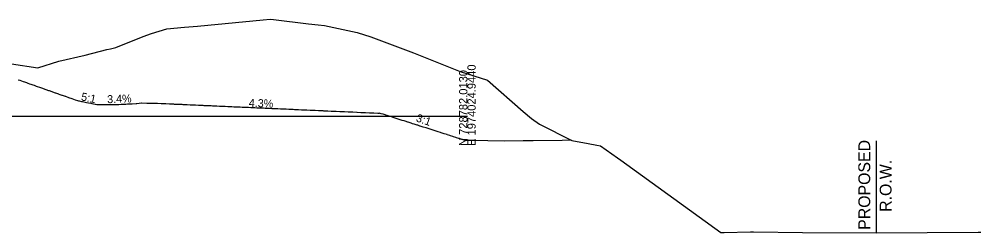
# Model space of a CAD drawing. Extents: x -26 to 630, y -39 to 9098.
# Drawn here: x 298.8 to 623.2, y 960.7 to 1032.7 of the extents above; entities that cross this region are included whole.
import ezdxf

# ---------------------------------------------------------------- set-up
doc = ezdxf.new("R2010")
doc.units = 0
for name, color, linetype in [('CONST_DCH', 7, 'Continuous'), ('Default', 7, 'Continuous'), ('DTM_X_FLOW_ARROWS', 7, 'Continuous'), ('DTM_X_GROUND', 7, 'Continuous'), ('XS_CELL', 7, 'Continuous'), ('XS_P_GROUND', 7, 'Continuous'), ('XS_P_ROW', 7, 'Continuous'), ('XS_P_TX_FS_BS', 7, 'Continuous')]:
    doc.layers.add(name, color=color, linetype=linetype)

msp = doc.modelspace()

# ---------------------------------------------------------------- linework, layer by layer
at = {"layer": 'DTM_X_GROUND'}
msp.add_lwpolyline([(296.18, 1017.68), (305.07, 1016.38), (312.1, 1018.55), (321.05, 1020.57), (328.36, 1022.58), (329.58, 1022.72), (331.34, 1023.24), (340.58, 1026.88), (343.46, 1027.9), (348.54, 1029.53), (354.5, 1030), (358.9, 1030.39), (381.1, 1032.55), (383.47, 1032.72), (384.56, 1032.65), (396.39, 1031.17), (399.69, 1030.79), (401.77, 1030.66), (412.78, 1028.2), (417.41, 1026.75), (431.84, 1021.4), (447.6, 1015.09), (456.8, 1012.18), (468.77, 1001.66), (471.65, 999.21), (474.32, 997.31), (485.24, 991.82), (490.72, 990.82), (493.73, 990.31), (494.95, 990.08), (500.68, 985.98), (501.78, 985.16), (535.48, 960.84), (536.66, 960.86), (545.52, 961.02), (546, 961.02), (546.53, 961.03), (563.07, 960.84), (587.95, 960.74), (622.38, 960.95), (623.24, 960.89)], dxfattribs=at)
at = {"layer": 'XS_CELL'}
msp.add_line((100, 1000), (450, 1000), dxfattribs=at)
at = {"layer": 'XS_P_GROUND'}
for points in [[(298.44, 1012.33), (298.98, 1012.14), (299.51, 1011.95), (300.08, 1011.75), (300.58, 1011.58), (301.18, 1011.37), (301.65, 1011.2), (302.27, 1010.98), (302.72, 1010.83), (303.37, 1010.6), (303.78, 1010.45), (304.47, 1010.21), (304.85, 1010.08), (305.57, 1009.83), (305.92, 1009.7), (306.66, 1009.44), (307.45, 1009.16), (307.76, 1009.06), (308.65, 1008.74), (308.86, 1008.67), (309.78, 1008.35), (309.96, 1008.29), (310.9, 1007.95), (311.05, 1007.9), (312.03, 1007.56), (312.15, 1007.51), (313.15, 1007.16), (313.25, 1007.13), (314.27, 1006.77), (314.35, 1006.74), (315.39, 1006.38), (315.44, 1006.36), (316.51, 1005.98), (316.54, 1005.97), (317.63, 1005.59), (317.64, 1005.59), (318.38, 1005.33), (318.74, 1005.25), (318.94, 1005.21), (318.96, 1005.2), (319.05, 1005.19), (319.84, 1005.02), (320.13, 1004.96), (320.97, 1004.78), (321.5, 1004.68), (322.13, 1004.55), (322.92, 1004.39), (323.3, 1004.31), (324.39, 1004.1), (324.51, 1004.08), (324.97, 1003.99)], [(324.97, 1003.99), (325.74, 1003.97), (325.8, 1003.97), (327, 1003.96), (327.18, 1003.96), (328.29, 1003.96), (328.61, 1003.96), (329.62, 1003.97), (330.07, 1003.98), (330.98, 1003.99), (331.59, 1004.02), (332.38, 1004.03), (333.17, 1004.07), (333.83, 1004.09), (334.8, 1004.15), (335.32, 1004.17), (336.5, 1004.24), (336.86, 1004.26), (338.26, 1004.36), (338.45, 1004.37), (340.08, 1004.5), (340.1, 1004.5), (340.1, 1004.5), (341.82, 1004.46), (341.9, 1004.46), (343.59, 1004.43), (343.73, 1004.44), (345.16, 1004.42), (345.36, 1004.41), (345.38, 1004.41), (346.67, 1004.35), (346.81, 1004.34), (348.07, 1004.29), (348.24, 1004.28), (349.47, 1004.22), (349.67, 1004.22), (350.87, 1004.16), (351.1, 1004.15), (352.27, 1004.1), (352.53, 1004.09), (353.67, 1004.04), (353.97, 1004.02), (355.08, 1003.97), (355.4, 1003.96), (356.48, 1003.91), (356.83, 1003.9), (357.88, 1003.85), (358.26, 1003.83), (359.29, 1003.79), (359.69, 1003.77), (360.69, 1003.72), (361.12, 1003.7), (362.09, 1003.66), (362.55, 1003.64), (363.5, 1003.6), (363.99, 1003.58), (364.9, 1003.53), (365.42, 1003.51), (366.31, 1003.47), (366.85, 1003.45), (367.71, 1003.41), (368.28, 1003.38), (369.12, 1003.35), (369.71, 1003.32), (370.52, 1003.28), (371.14, 1003.25), (371.93, 1003.22), (372.57, 1003.19), (373.33, 1003.16), (374.01, 1003.13), (374.74, 1003.09), (375.44, 1003.06), (376.14, 1003.03), (376.87, 1003), (377.55, 1002.97), (378.3, 1002.93), (378.96, 1002.91), (379.73, 1002.87), (380.36, 1002.84), (381.16, 1002.81), (381.77, 1002.78), (382.59, 1002.74), (383.18, 1002.72), (384.03, 1002.68), (384.58, 1002.65), (385.46, 1002.61), (385.99, 1002.59), (386.89, 1002.55), (387.4, 1002.53), (388.32, 1002.49), (388.81, 1002.47), (389.75, 1002.42), (390.21, 1002.4), (391.18, 1002.36), (391.62, 1002.34), (392.61, 1002.29), (393.03, 1002.28), (394.05, 1002.23), (394.44, 1002.21), (395.48, 1002.17), (395.85, 1002.15), (396.91, 1002.1), (397.26, 1002.09), (398.34, 1002.04), (398.67, 1002.02), (399.77, 1001.97), (400.08, 1001.96), (401.2, 1001.91), (401.48, 1001.9), (402.63, 1001.85), (402.89, 1001.84), (404.07, 1001.78), (404.3, 1001.77), (405.5, 1001.72), (405.71, 1001.71), (406.93, 1001.65), (407.12, 1001.65), (408.36, 1001.59), (408.53, 1001.58), (409.79, 1001.53), (409.94, 1001.52), (411.22, 1001.46), (411.35, 1001.46), (412.65, 1001.4), (412.76, 1001.39), (414.09, 1001.33), (414.18, 1001.33), (415.52, 1001.27), (415.59, 1001.27), (416.95, 1001.21), (417, 1001.2), (418.38, 1001.14), (418.41, 1001.14), (419.81, 1001.08), (419.82, 1001.08), (420.37, 1001.05)], [(484.97, 991.94), (482, 991.85), (472.17, 991.69), (472.14, 991.69), (468.77, 991.68), (462.39, 991.66), (456.91, 991.73), (452.57, 991.79), (449.88, 991.87), (449.18, 991.89), (448.37, 992.15), (448.17, 992.21), (447.34, 992.48), (447.16, 992.53), (446.31, 992.8), (446.15, 992.85), (445.28, 993.13), (445.14, 993.18), (444.25, 993.46), (444.13, 993.5), (443.23, 993.78), (443.12, 993.82), (442.2, 994.11), (442.11, 994.14), (441.88, 994.21), (441.86, 994.22), (441.16, 994.44), (441.1, 994.46), (440.97, 994.5), (440.96, 994.5), (440.15, 994.76), (440.09, 994.78), (439.13, 995.09), (439.08, 995.1), (438.11, 995.41), (438.07, 995.43), (437.09, 995.74), (437.05, 995.75), (436.06, 996.06), (436.04, 996.07), (435.04, 996.39), (435.03, 996.39), (434.02, 996.71), (434.02, 996.71), (433.96, 996.73), (433.25, 996.96), (433.03, 997.03), (433.01, 997.03), (433, 997.04), (432, 997.35), (431.5, 997.51), (430.99, 997.68), (430.03, 997.98), (429.98, 998), (429.86, 998.03), (428.97, 998.32), (428.64, 998.42), (427.96, 998.64), (427.27, 998.86), (426.95, 998.96), (425.97, 999.27), (425.93, 999.28), (425.92, 999.29), (424.92, 999.6), (424.41, 999.77), (423.91, 999.93), (422.93, 1000.24), (422.9, 1000.25), (422.85, 1000.26), (421.89, 1000.57), (421.54, 1000.68), (420.91, 1000.88), (420.88, 1000.89), (420.37, 1001.05)]]:
    msp.add_lwpolyline(points, dxfattribs=at)
at = {"layer": 'XS_P_ROW'}
msp.add_line((587.95, 991.76), (587.95, 960.74), dxfattribs=at)

# ---------------------------------------------------------------- texts
at = {"layer": 'CONST_DCH'}
for p in [(324.97, 1003.99), (324.97, 1003.99), (340.08, 1004.5)]:
    msp.add_text('X', height=0.001, dxfattribs=at).set_placement(p)
at = {"layer": 'Default'}
msp.add_text('X', height=0.001, dxfattribs=at).set_placement((420.36, 1001.05))
at = {"layer": 'DTM_X_FLOW_ARROWS'}
msp.add_text('X', height=0.001, dxfattribs=at).set_placement((318.38, 1005.33))
at = {"layer": 'XS_CELL'}
for s, p in [('E 1974024.9440', (452.8, 990)), ('N 728782.0130', (450, 990))]:
    msp.add_text(s, height=2.8, rotation=90, dxfattribs=at).set_placement(p)
at = {"layer": 'XS_P_ROW'}
for s, p in [('PROPOSED', (585.93, 961.72)), ('R.O.W.', (593.13, 967.79))]:
    msp.add_text(s, height=4, rotation=90, dxfattribs=at).set_placement(p)
at = {"layer": 'XS_P_TX_FS_BS'}
for s, rotation, p in [('5:1', 348.5146, (319.48, 1005.41)), ('3.4%', 1.9339, (328.49, 1004.41)), ('4.3%', 357.5423, (376.21, 1003.25)), ('3:1', 340.7077, (432.47, 998.37))]:
    msp.add_text(s, height=2.7, rotation=rotation, dxfattribs=at).set_placement(p)

doc.saveas('drawing.dxf')
